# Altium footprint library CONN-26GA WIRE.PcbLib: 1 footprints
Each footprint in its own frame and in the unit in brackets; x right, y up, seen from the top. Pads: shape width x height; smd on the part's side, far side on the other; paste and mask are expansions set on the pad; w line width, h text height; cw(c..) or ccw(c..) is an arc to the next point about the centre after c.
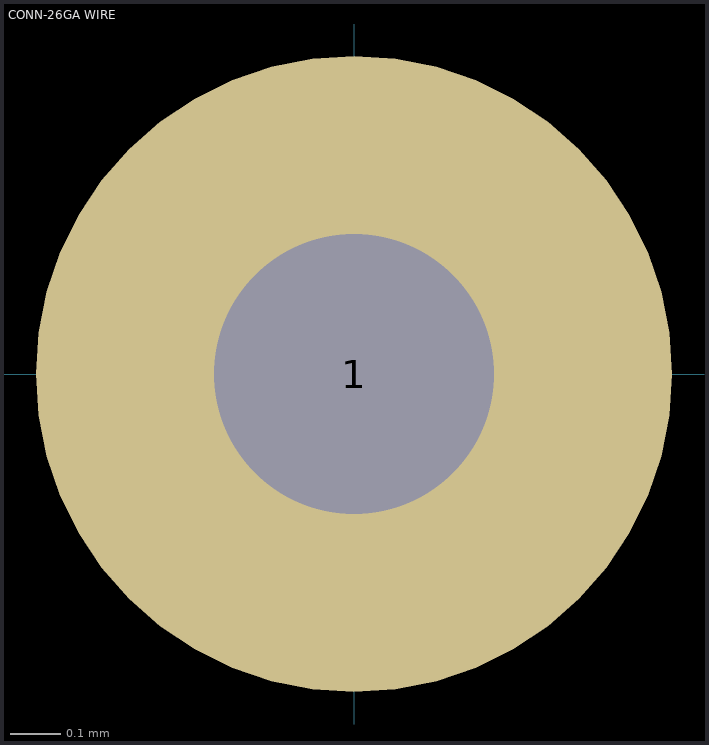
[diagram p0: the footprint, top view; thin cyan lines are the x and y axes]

## CONN-26GA WIRE [mil]
height 84.65
pads (1):
  round 50 hole 22: 1(0,0)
